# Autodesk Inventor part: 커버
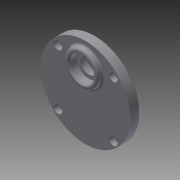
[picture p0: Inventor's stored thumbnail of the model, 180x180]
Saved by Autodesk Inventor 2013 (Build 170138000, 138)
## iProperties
Created: 2015-07
Part Number: 커버
Material: 일반
Document SubType Name: Modeling
Designer: user
Density: 1 g/cm^3
Author: user
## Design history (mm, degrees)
sketch "스케치1"
  geometry: C1 r 40 at (0, 0); 1 further point
  constraints: 1 centre point, 1 coincident
  dimensions: "d0" = 80 diameter of C1
extrude "돌출1" new body sketch "스케치1" distance "d1" = 9; taper "d2" = 0 deg
sketch "스케치2"
  geometry: L1 (0, 0)-(0, 11); L2 (0, 0)-(0, -20); C1 r 40 at (0, 0) reference; C2 r 14 at (0, 11); C3 r 14 at (0, -20)
  constraints: 4 end point, 2 centre point, 2 coincident, 1 collinear, 1 vertical
  dimensions: "d3" = 11 distance of L1.start L1.end; "d4" = 28 diameter of C2; "d5" = 20 distance of L1.start L2.end; "d6" = 28 diameter of C3
extrude "돌출2" join sketch "스케치2" distance "d7" = 3; taper "d8" = 0 deg
sketch "스케치3"
  geometry: L1 (0, 0)-(0, 20); C1 r 40 at (0, 0) reference; C2 r 15 at (0, 20)
  constraints: 2 end point, 1 centre point, 1 coincident, 1 vertical
  dimensions: "d9" = 20 distance of L1.start L1.end; "d10" = 30 diameter of C2
extrude "돌출3" join sketch "스케치3" distance "d11" = 4; taper "d12" = 0 deg
sketch "스케치4"
  geometry: C1 r 15 at (0, 0) reference; C2 r 11 at (0, 0); 1 further point
  constraints: 1 centre point, 1 coincident
  dimensions: "d13" = 22 diameter of C2
extrude "돌출4" cut sketch "스케치4" distance "d14" = 7; taper "d15" = 0 deg
sketch "스케치5"
  geometry: C1 r 11 at (0, 0) reference; C2 r 7.5 at (0, 0); 1 further point
  constraints: 1 centre point, 1 coincident
  dimensions: "d16" = 15 diameter of C2
extrude "돌출5" cut sketch "스케치5" distance "d17" = 2; taper "d18" = 0 deg
sketch "스케치6"
  geometry: C1 r 14 at (0, 0) reference; C2 r 11 at (0, 0); 1 further point
  constraints: 1 centre point, 1 coincident
  dimensions: "d19" = 22 diameter of C2
extrude "돌출6" cut sketch "스케치6" distance "d20" = 7; taper "d21" = 0 deg
sketch "스케치7"
  geometry: C1 r 14 at (0, 0) reference; C2 r 11 at (0, 0); 1 further point
  constraints: 1 centre point, 1 coincident
  dimensions: "d22" = 22 diameter of C2
extrude "돌출7" cut sketch "스케치7" distance "d23" = 7; taper "d24" = 0 deg
sketch "스케치8"
  geometry: C1 r 9 at (0, 0); 2 further points
  constraints: 1 centre point, 1 coincident, 1 vertical alignment
  dimensions: "d25" = 18 diameter of C1
extrude "돌출8" cut sketch "스케치8" distance "d26" = 1; taper "d27" = 0 deg
sketch "스케치9"
  geometry: L1 (0, 0)-(24.749, 24.749); L2 (0, 0)-(35, 0); C1 r 40 at (0, 0) reference; C2 r 4 at (24.749, 24.749); C3 r 4 at (-24.749, 24.749); C4 r 4 at (-24.749, -24.749); C5 r 4 at (24.749, -24.749); A1 r 35 centre (0, 0) between (24.749, 24.749) and (35, 0)
  constraints: 5 centre point, 4 end point, 2 coincident, 2 point on circle, 1 horizontal, 9 other
  dimensions: "d28" = 70 diameter of A1; "d29" = 45 deg angle of L2 L1; "d31" = 8 diameter of C2; "d34" = 360 deg dimension on C1.centre C2.centre (derived)
extrude "돌출9" cut sketch "스케치9" distance "d36" = 4.4; taper "d37" = 0 deg
sketch "스케치10"
  geometry: C1 r 4 at (0, 0) reference; C2 r 2.25 at (0, 0); 1 further point
  constraints: 1 centre point, 1 coincident
  dimensions: "d38" = 4.5 diameter of C2
extrude "돌출10" cut sketch "스케치10" distance "d39" = 10; taper "d40" = 0 deg
chamfer "모따기1" distance "d44" = 1; stored, may be unused: second distance "d45" = 2, angle "d46" = 45 deg
fillet "모깎기1" dims "d47" = 2
fillet "모깎기2" dims "d48" = 2
fillet "모깎기3" dims "d49" = 0.3
chamfer "모따기2" distance "d50" = 1; stored, may be unused: second distance "d51" = 2, angle "d52" = 45 deg
node "솔리드1"
pattern_circular "원형 패턴1" dims angle "d42" = 360 deg
